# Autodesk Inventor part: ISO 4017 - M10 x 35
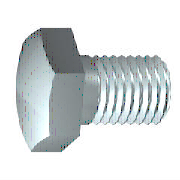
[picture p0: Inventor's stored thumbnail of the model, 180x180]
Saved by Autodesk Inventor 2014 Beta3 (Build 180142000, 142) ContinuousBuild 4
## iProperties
Created: 2010-11
Part Number: ISO 4017 - M10 x 35
Material: Stainless Steel, 440C
Description: Hexagon head screws
Document SubType Name: Modeling
Standard: ISO 4017
Designer: Thom Tremblay
Standard Revision: Third edition 1999-08-15
Standards Organization: ISO
Language: en-US
Size Designation: M10 x 35
Categories: <MemberInstance><Categories><Category DisplayName="Fasteners" InternalName="e4da775c-781d-43d5-af7c-5136215cf5a6" Mnemonic="FSTN"><Category DisplayName="Bolts"
Density: 7.75 g/cm^3
Appearance: Steel
IsCustomPart: 0
Author: Thom Tremblay
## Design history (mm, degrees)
sketch "Sketch1"
  geometry: L1 (0, 7.315)-(0, 5); L2 (4.5, 5)-(35, 5); L3 (35, 5)-(35, 0); L4 (35, 0)-(-0.6, 0); L5 (-7.72, 0)-(42.12, 0) reference; L6 (-0.6, 0)-(-0.6, 7.315); L7 (-0.6, 7.315)-(0, 7.315); L8 (4.5, 5)-(3.58, 5); L9 (3.58, 5)-(0, 5); L10 (0, -1.463)-(0, 8.778) reference
  constraints: 16 end point, 2 collinear, 2 perpendicular, 1 parallel
  dimensions: "d0" = 35 distance between parallel lines of L3 L1 (= NLG); "d1" = 30.5 distance from line of L2.start L3 (= GEL); "d2" = 10 diameter of L2 L4 (= GD); "d9" = 0.6001 distance between parallel lines of L6 L1 (computed from SD); "d10" = 14.63 diameter of L7 L4 (= SD2); "d13" = 0.92028 distance of L2.start L8.end (computed from GAL); "d14" = 10 diameter of L9 L4 (= BDM)
revolve "Body" sketch "Sketch1" stored, may be unused: angle "d12" = 90 deg
sketch "Sketch2"
  geometry: L1 (0, 9.238)-(8, 4.619); L2 (8, 4.619)-(8, -4.619); L3 (8, -4.619)-(0, -9.238); L4 (0, -9.238)-(-8, -4.619); L5 (-8, -4.619)-(-8, 4.619); L6 (-8, 4.619)-(0, 9.238); 2 further points
  constraints: 12 end point, 1 coincident, 1 vertical, 11 other
  dimensions: "d11" = 16 distance between parallel lines of L5 L2 (= SW)
extrude "Head" join sketch "Sketch2" distance "d3" = 5.8 (= KOH - SD); taper "d4" = 0 deg
sketch "Sketch4"
  geometry: L1 (-6.4, 8)-(-6.4, 9.238); L2 (-6.4, 9.238)-(-5.686, 9.238); L3 (-5.686, 9.238)-(-6.4, 8); L4 (-7.56, 0)-(0.56, 0) reference; L5 (-0.6, 9.238)-(-6.4, 9.238) reference; L6 (-6.4, 4.619)-(-6.4, 9.238) reference
  constraints: 6 end point, 2 collinear, 1 perpendicular, 1 vertical
  dimensions: "d5" = 30 deg angle of L3 L1 (= ANG1); "d19" = 16 diameter of L1.start L4 (= SW0)
revolve "Chamfer1" sketch "Sketch4" stored, may be unused: angle "d21" = 90 deg
workplane "Work Plane1"
body "Solid1"
feature "Thread" dims "d15" = 30.5 (= GEL), "d16" = 0
chamfer "Chamfer2" distance "d6" = 0.92018 (= -0.5 x SPD + 0.5 x GD); stored, may be unused: second distance "d7" = 0.92028 (computed from GUL), angle "d55" = 45 deg
other parameters: "NLG" = 35 [user parameter; used in 1 equation term], "GD" = 10 (= NND) [user parameter; used in 2 equation terms], "BDM" = 10 (= NND) [user parameter; used in 1 equation term], "KOH" = 6.4 [user parameter; used in 1 equation term], "GEL" = 30.5 [user parameter; used in 2 equation terms], "SW" = 16 [user parameter; used in 2 equation terms], "SW0" = 16 (= SW) [user parameter; used in 1 equation term], "SPD" = 8.15965 (= NND - 1.2269 x PTC) [user parameter; used in 1 equation term], "SD2" = 14.63 [user parameter; used in 2 equation terms], "SD" = 0.6 [user parameter; used in 2 equation terms], "ANG1" = 30 deg [user parameter; used in 1 equation term], "GAL" = 0.92018 (= 0.61345 x PTC) [user parameter; used in 1 equation term], "GUL" = 0.92018 (= 0.61345 x PTC) [user parameter; used in 1 equation term], "d8" = 0, "RR" = 0.4 [user parameter], "d57" = 0, "d58" = 0, "TPU" = 6.66667 (computed from PTC) [user parameter], "GD1" = 8.15965 (= THREADDIA - 1.2269 x PTC) [user parameter], "SDH" = 14.63 (= SD2) [user parameter], "SDHG" = 4.5 [user parameter], "TOA" = 30 deg [user parameter], "PTC" = 1.5 [user parameter; used in 5 equation terms], "E0" = 18.48 [user parameter]
